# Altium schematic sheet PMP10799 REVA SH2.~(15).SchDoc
size 431 x 279 mm; Date: Not shown in title block; ApprovedBy: Not shown in title block; CheckedBy: Not shown in title block; Author: Not shown in title block; CompanyName: Not shown in title block; Engineer: Not shown in title block; Organization: Not shown in title block; Address1: Not shown in title block; Address2: Not shown in title block; Address3: Not shown in title block; Address4: Not shown in title block; DocumentNumber: 2; Revision: Use project parameter SCH_Rev; SheetNumber: 2; SheetTotal: 2; PageSetup: Record=PageOptions¦CenterHorizontal=True¦CenterVertical=True¦PrintScale=1.00¦XCorrection=1.00¦YCorrection=1.00¦PrintKind=0¦BorderSize=5000000¦LeftOffset=0¦BottomOffset=0¦Orientation=2¦PaperLength=1000¦PaperWidth=1000¦Scale=100¦PaperSource=15¦PrintQuality=600¦MediaType=1¦DitherType=10¦PaperKind=Letter¦PrintScaleMode=1
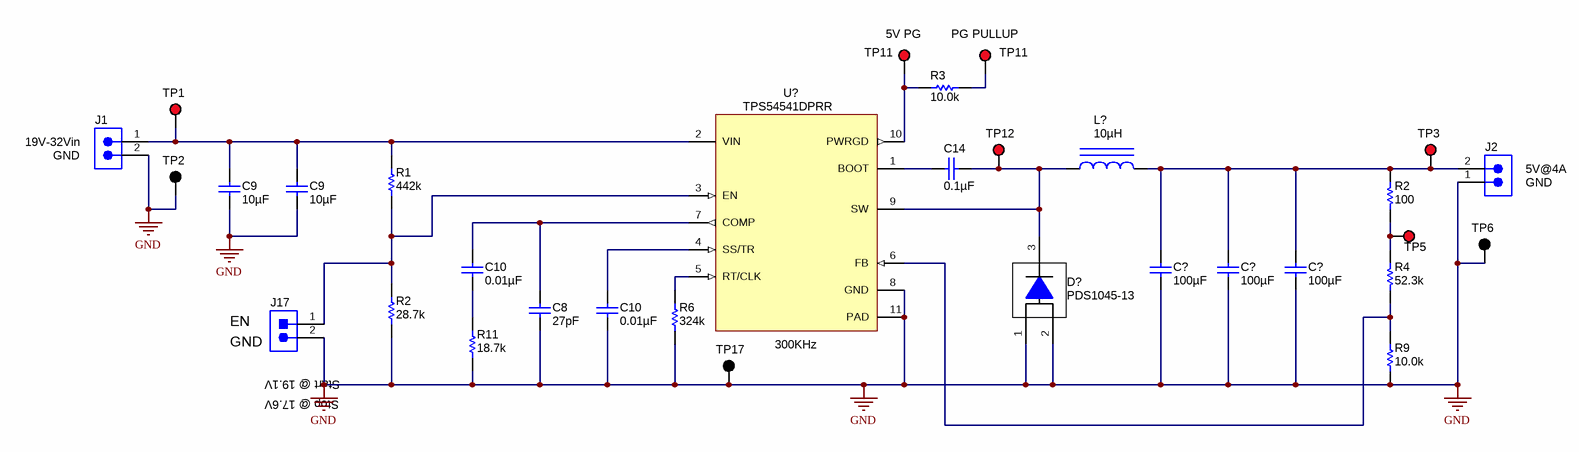
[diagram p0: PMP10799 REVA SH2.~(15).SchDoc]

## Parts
(Parts that share a designator on the sheet are numbered #1, #2 ... from top to bottom, then left to right.)
C8  ValueDisplayed: 27pF  [0603]  (hidden comment: C1608C0G1H270J)
C9#1  ValueDisplayed: 10µF  [1210]  (hidden comment: GRM32ER61H106MA12)
C9#2  ValueDisplayed: 10µF  [1210]  (hidden comment: GRM32ER61H106MA12)
C10#1  ValueDisplayed: 0.01µF  [0603]  (hidden comment: C1608X7R1H103K)
C10#2  ValueDisplayed: 0.01µF  [0603]  (hidden comment: C1608X7R1H103K)
C14  ValueDisplayed: 0.1µF  [0603]  (hidden comment: C1608X7R1H104K)
C?#1  ValueDisplayed: 100µF  [1210]  (hidden comment: GRM32EC80J107ME20)
C?#2  ValueDisplayed: 100µF  [1210]  (hidden comment: GRM32EC80J107ME20)
C?#3  ValueDisplayed: 100µF  [1210]  (hidden comment: GRM32EC80J107ME20)
D?  PDS1045-13  [PowerDI5]
J1  ED555/2DS  [TERM_BLK_ED555-2DS]  (value not drawn)
J2  ED555/2DS  [TERM_BLK_ED555-2DS]  (value not drawn)
J17  PEC02SAAN  [CONN_PEC02SAAN]  (value not drawn)
L?  ValueDisplayed: 10µH  [XAL8080_656]  (hidden comment: XAL8080-103ME)
R1  ValueDisplayed: 442k  [0603]  (hidden comment: CRCW0603442KFKEA)
R2#1  ValueDisplayed: 100  [0603L]  (hidden comment: CRCW0603100RFKEA)
R2#2  ValueDisplayed: 28.7k  [0603]  (hidden comment: CRCW060328K7FKEA)
R3  ValueDisplayed: 10.0k  [0603]  (hidden comment: CRCW060310K0FKEA)
R4  ValueDisplayed: 52.3k  [0603L]  (hidden comment: CRCW060352K3FKEA)
R6  ValueDisplayed: 324k  [0603]  (hidden comment: CRCW0603324KFKEA)
R9  ValueDisplayed: 10.0k  [0603L]  (hidden comment: CRCW060310K0FKEA)
R11  ValueDisplayed: 18.7k  [0603]  (hidden comment: CRCW060318K7FKEA)
TP1  5000  [Keystone5000]  (value not drawn)
TP2  5001  [Keystone5001]  (value not drawn)
TP3  5000  [Keystone5000]  (value not drawn)
TP5  5000  [Keystone5000]  (value not drawn)
TP6  5001  [Keystone5001]  (value not drawn)
TP11#1  5000  [Keystone5000]  (value not drawn)
TP11#2  5000  [Keystone5000]  (value not drawn)
TP12  5000  [Keystone5000]  (value not drawn)
TP17  5001  [Keystone5001]  (value not drawn)
U?  TPS54541DPRR  [DPR0010A]

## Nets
GND: C8.2 C9#1.1 C9#2.1 C10#2.2 C?#1.2 C?#2.2 C?#3.2 D?.1(A) D?.2(A) J1.2 J2.1 J17.2 R2#2.1 R6.1 R9.1 R11.1 TP2.1 TP6.1 TP17.1 U?.8(GND) U?.11(PAD)
NetC8_1: C8.1 C10#1.1 U?.7(COMP)
NetC9#1_2: C9#1.2 C9#2.2 J1.1 R1.2 TP1.1 U?.2(VIN)
NetC10#1_2: C10#1.2 R11.2
NetC10#2_1: C10#2.1 U?.4(SS/TR)
NetC14_1: C14.1 U?.1(BOOT)
NetC14_2: C14.2 D?.3(K) L?.1 TP12.1 U?.9(SW)
NetC?#1_1: C?#1.1 C?#2.1 C?#3.1 J2.2 L?.2 R2#1.2 TP3.1
NetJ17_1: J17.1 R1.1 R2#2.2 U?.3(EN)
NetR2#1_1: R2#1.1 R4.2 TP5.1
NetR3_1: R3.1 TP11#2.1
NetR3_2: R3.2 TP11#1.1 U?.10(PWRGD)
NetR4_1: R4.1 R9.2 U?.6(FB)
NetR6_2: R6.2 U?.5(RT/CLK)

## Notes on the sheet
- (near TP11#1) 5V PG
- (near TP11#2) PG PULLUP
- (near J1) 19V-32Vin
- (near J1) GND
- (near J2) 5V@4A
- (near J2) GND
- (near J17) EN
- (near J17) GND
- (near U?) 300KHz
- (near J17) Start @ 19.1V
- Stop @ 17.6V

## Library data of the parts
C8 = C1608C0G1H270J: CAP, CERM, 27 pF, 50 V, +/- 5%, C0G/NP0, 0603; Manufacturer: TDK; Polarized: N; CompType: Capacitor; Value: 27pF; U/M: EA; Cap_F: 0.000000000027; Tolerance_%: 5; ESR_ohm: 0.327; Value1: 0.327 ohm; VDC_V: 50; Value2: 50V; TaMin_C: -55; TaMax_C: 125
C9#1 C9#2 = C3225X7R1E106M: CAP, CERM, 10uF, 50V, +/-20%, X5R, 1210; Manufacturer: MuRata; Polarized: N; CompType: Capacitor; U/M: EA; Cap_F: 0.00001; Tolerance_%: 20; ESR_Ohm: 0.0027; Value1: 0.0027 ohm; VDC_V: 50; IRMS_A: 3; TaMin_C: -55; TaMax_C: 125
C10#1 C10#2 = C1608X7R1H103K: CAP, CERM, 0.01 µF, 50 V, +/- 10%, X7R, 0603; Manufacturer: TDK; Polarized: N; CompType: Capacitor; Value: 0.01uF; U/M: EA; Cap_F: 0.00000001; Tolerance_%: 10; ESR_ohm: 0.0539; Value1: 0.0539 ohm; VDC_V: 50; Value2: 50V; TaMin_C: -55; TaMax_C: 125
C14 = C1608X7R1H104K: CAP, CERM, 0.1uF, 50V, +/-10%, X7R, 0603; Manufacturer: TDK; Polarized: N; CompType: Capacitor; U/M: EA; Cap_F: 0.0000001; Tolerance_%: 10; ESR_Ohm: 0.017; Value1: 0.017 ohm; VDC_V: 50; TaMin_C: -55; TaMax_C: 125
C?#1-C?#3 = C3225X5R0J107M: CAP, CERM, 100 µF, 6.3 V, +/- 20%, X6S, 1210; Manufacturer: MuRata; Polarized: N; CompType: Capacitor; Value: 100uF; U/M: EA; Cap_F: 0.0001; Tolerance_%: 20; ESR_ohm: 0.002; Value1: 0.002 ohm; VDC_V: 6.3; Value2: 6.3V; IRMS_A: 3.5; TaMin_C: -55; TaMax_C: 85
D? = PDS1045-13: Diode, Schottky, 45 V, 10 A, PowerDI5; Manufacturer: Diodes Inc.; SymbolCreator: a0412235; U/M: EA; Vf_V: 0.51; Value: 45V; Value1: 10A; Value2: 0.51V; Io_A: 10; Vr_V: 45; TJmax_C: 150; RJC_CperW: 85
J1 J2 = ED555/2DS: Terminal Block, 6A, 3.5mm Pitch, 2-Pos, TH; Manufacturer: On-Shore Technology, Inc.; SymbolCreator: a0412235; CompType: Connector; U/M: EA
J17 = PEC02SAAN: Header, 100mil, 2x1, Tin, TH; Manufacturer: Sullins Connector Solutions; SymbolCreator: a0412235; U/M: EA
L? = XAL8080-472ME: Inductor, Shielded, Composite, 10 µH, 8.7 A, 0.021 ohm, SMD; Manufacturer: Coilcraft; Value: 10uH; Ind_H: 10E-6; Imax_A: 8.7; Irms: 6.6A @ 20C rise; Isat: 10.9A @ 20% inductance drop; DCR_ohm: 21; Value2: 8.7A
R1 = CRCW0603442KFKEA: RES, 442 k, 1%, 0.1 W, 0603; Manufacturer: Vishay-Dale; CompType: Resistor; Value: 442k; Res_ohm: 442000; Tolerance_%: 1; Power_W: 0.1; Value2: 0.1W; VDC_V: 75; TempCo: 100 ppm/C; EIA_Code: E96; U/M: EA
R2#1 = CRCW0603100RFKEA: RES, 100, 1%, 0.1 W, 0603; Manufacturer: Vishay-Dale; CompType: Resistor; Value: 100; Value_Code: 100R; Tolerance_%: 1; Power_W: 0.1; Value2: 0.1W; VDC_V: 75; TempCo: 100 ppm/C; EIA_Code: E96; U/M: EA
R2#2 = CRCW060328K7FKEA: RES, 28.7 k, 1%, 0.1 W, 0603; Manufacturer: Vishay-Dale; CompType: Resistor; Value: 28.7k; Res_ohm: 28700; Value_Code: 28k7; Tolerance_%: 1; Power_W: 0.1; Value2: 0.1W; VDC_V: 75; TempCo: 100 ppm/C; EIA_Code: E96; U/M: EA
R3 R9 = CRCW060310K0FKEA: RES, 10.0 k, 1%, 0.1 W, 0603; Manufacturer: Vishay-Dale; CompType: Resistor; Value: 10.0k; Res_ohm: 10000; Value_Code: 10k0; Tolerance_%: 1; Power_W: 0.1; Value2: 0.1W; VDC_V: 75; TempCo: 100 ppm/C; EIA_Code: E96; U/M: EA
R4 = CRCW060352K3FKEA: RES, 52.3 k, 1%, 0.1 W, 0603; Manufacturer: Vishay-Dale; CompType: Resistor; Value: 52.3k; Res_ohm: 52300; Value_Code: 52k3; Tolerance_%: 1; Power_W: 0.1; Value2: 0.1W; VDC_V: 75; TempCo: 100 ppm/C; EIA_Code: E96; U/M: EA
R6 = CRCW0603324KFKEA: RES, 324 k, 1%, 0.1 W, 0603; Manufacturer: Vishay-Dale; CompType: Resistor; Value: 324k; Res_ohm: 324000; Tolerance_%: 1; Power_W: 0.1; Value2: 0.1W; VDC_V: 75; TempCo: 100 ppm/C; EIA_Code: E96; U/M: EA
R11 = CRCW060318K7FKEA: RES, 18.7 k, 1%, 0.1 W, 0603; Manufacturer: Vishay-Dale; CompType: Resistor; Value: 18.7k; Res_ohm: 18700; Value_Code: 18k7; Tolerance_%: 1; Power_W: 0.1; Value2: 0.1W; VDC_V: 75; TempCo: 100 ppm/C; EIA_Code: E96; U/M: EA
TP1 TP3 TP5 TP11#1 TP11#2 TP12 = 5000: Test Point, TH, Miniature, Red; Manufacturer: Keystone; CompType: Test Point Loop; U/M: EA
TP2 TP6 TP17 = 5001: Test Point, TH, Miniature, Black; Manufacturer: Keystone; CompType: Test Point Loop; U/M: EA
U? = TPS54361DPRQ1: 4.5-V to 42-V Input, 5-A, Step Down DC-DC Converter with Soft-Start and Eco-mode, DPR0010A; Alternate Manufacturer: None; Manufacturer: Texas Instruments; SymbolCreator: a0411947; CompType: IC; U/M: EA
